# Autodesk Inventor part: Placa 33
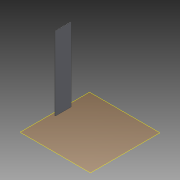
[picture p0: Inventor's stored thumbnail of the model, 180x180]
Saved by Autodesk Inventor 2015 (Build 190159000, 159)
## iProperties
Created: 2015-04
Part Number: Placa 33
Material: Generic
Document SubType Name: Modeling
Designer: suporte
Density: 1 g/cm^3
Appearance: Default
Author: suporte
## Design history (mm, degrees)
workplane "Work Plane1"
sketch "Sketch1"
  geometry: L1 (-900, -87.5)-(-912.5, -87.5) reference; L2 (-912.5, -87.5)-(-900, -87.5); L3 (-900, -87.5)-(-900, 362.5); L4 (-900, 362.5)-(-912.5, 362.5); L5 (-912.5, 362.5)-(-912.5, -87.5); 1 further point
  constraints: 8 end point, 2 parallel, 1 horizontal, 1 perpendicular
  dimensions: "d0" = 12.5 distance of L4.end L3.end; "d1" = 450 distance of L3.end L2.end
extrude "Extrusion1" new body sketch "Sketch1" distance "d2" = 2100; taper "d3" = 0 deg
body "Solid1"
node "Reference1"
